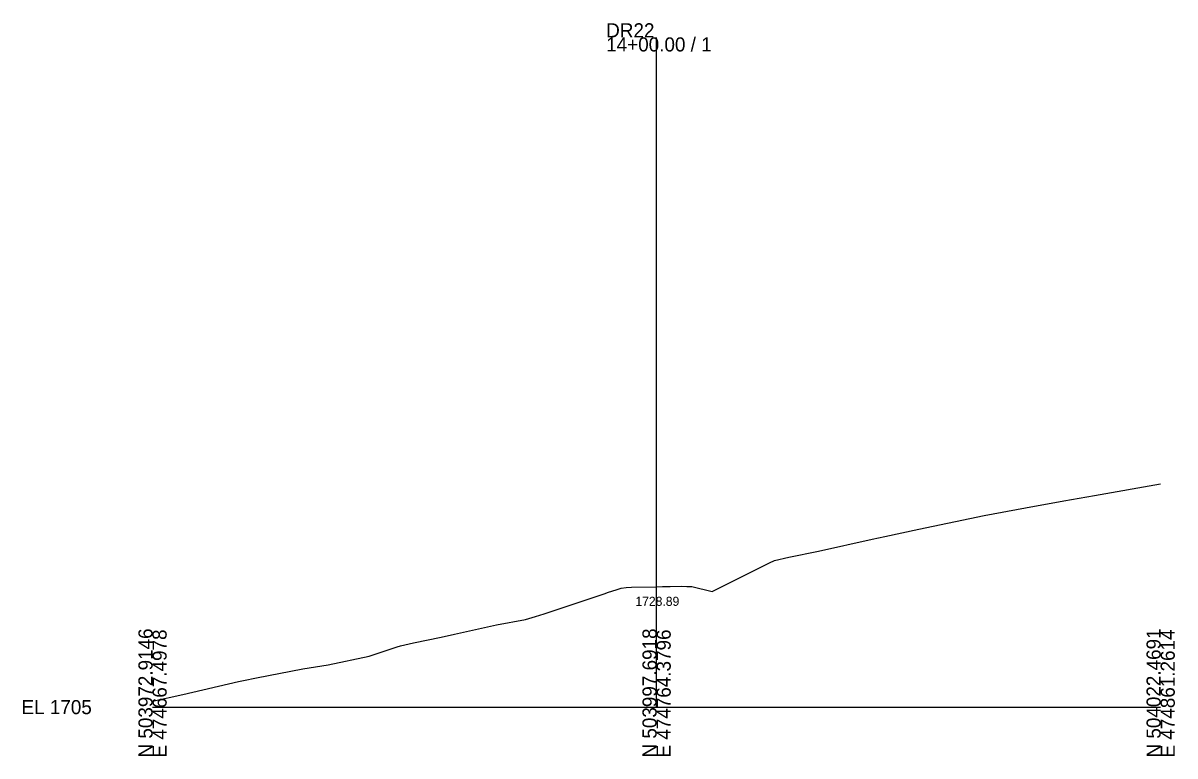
# Model space of a CAD drawing. Extents: x -26 to 1203, y -10 to 9633.
# Drawn here: x 974.3 to 1202.8, y -9.7 to 135.7 of the extents above; entities that cross this region are included whole.
import ezdxf

# ---------------------------------------------------------------- set-up
doc = ezdxf.new("R2010")
doc.units = 0
for name, color, linetype in [('Exist Cross Section Cell', 7, 'Continuous'), ('Exist XS Center Line Elevation Label', 7, 'Continuous'), ('Exist XS Ground Line', 7, 'Continuous'), ('Scratch_Level_5', 7, 'Continuous')]:
    doc.layers.add(name, color=color, linetype=linetype)

msp = doc.modelspace()

# ---------------------------------------------------------------- linework, layer by layer
at = {"layer": 'Exist Cross Section Cell'}
for p, q in [((1100, 0), (1100, 132.88)), ((1000, 0), (1100, 0)), ((1100, 0), (1200, 0))]:
    msp.add_line(p, q, dxfattribs=at)
at = {"layer": 'Exist XS Ground Line'}
msp.add_lwpolyline([(1000, 1.16), (1006.01, 2.48), (1017.02, 5.05), (1018.07, 5.29), (1020.62, 5.8), (1029.81, 7.57), (1034.86, 8.42), (1042.95, 10.12), (1048.51, 11.97), (1049.18, 12.13), (1051.79, 12.74), (1057.26, 13.9), (1059.92, 14.48), (1068.21, 16.31), (1073.96, 17.39), (1076, 17.97), (1077.69, 18.53), (1089, 22.3), (1089.81, 22.57), (1090.29, 22.73), (1092.16, 23.35), (1093, 23.63), (1093.98, 23.71), (1095, 23.79), (1100, 23.89), (1101.18, 23.92), (1102.69, 23.95), (1105, 23.99), (1106.02, 23.95), (1107, 23.91), (1111, 22.91), (1116.19, 25.51), (1118.86, 26.84), (1122.37, 28.6), (1123.38, 29.11), (1126.24, 29.76), (1132.1, 30.95), (1142.79, 33.32), (1145.27, 33.88), (1152.02, 35.32), (1164.98, 38), (1173.21, 39.54), (1180.8, 40.9), (1186.87, 41.96), (1200, 44.29)], dxfattribs=at)
at = {"layer": 'Scratch_Level_5'}
msp.add_lwpolyline([(1000, 1.16), (1006.01, 2.48), (1017.02, 5.05), (1018.07, 5.29), (1020.62, 5.8), (1029.81, 7.57), (1034.86, 8.42), (1042.95, 10.12), (1048.51, 11.97), (1049.18, 12.13), (1051.79, 12.74), (1057.26, 13.9), (1059.92, 14.48), (1068.21, 16.31), (1073.96, 17.39), (1076, 17.97), (1077.69, 18.53), (1089, 22.3), (1089.81, 22.57), (1090.29, 22.73), (1092.16, 23.35), (1093, 23.63), (1093.98, 23.71), (1095, 23.79), (1100, 23.89), (1101.18, 23.92), (1102.69, 23.95), (1105, 23.99), (1106.02, 23.95), (1107, 23.91), (1111, 22.91), (1116.19, 25.51), (1118.86, 26.84), (1122.37, 28.6), (1123.38, 29.11), (1126.24, 29.76), (1132.1, 30.95), (1142.79, 33.32), (1145.27, 33.88), (1152.02, 35.32), (1164.98, 38), (1173.21, 39.54), (1180.8, 40.9), (1186.87, 41.96), (1200, 44.29)], dxfattribs=at)

# ---------------------------------------------------------------- texts
at = {"layer": 'Exist Cross Section Cell'}
for s, p in [('DR22', (1090, 132.88)), ('14+00.00 / 1', (1090, 130.08)), ('EL 1705', (974, -1.4))]:
    msp.add_text(s, height=2.8, dxfattribs=at).set_placement(p)
for s, p in [('N 503972.9146', (1000, -10)), ('E 474667.4978', (1002.8, -10)), ('N 503997.6918', (1100, -10)), ('E 474764.3796', (1102.8, -10)), ('N 504022.4691', (1200, -10)), ('E 474861.2614', (1202.8, -10))]:
    msp.add_text(s, height=2.8, rotation=90, dxfattribs=at).set_placement(p)
at = {"layer": 'Exist XS Center Line Elevation Label'}
msp.add_text('1728.89', height=1.8, dxfattribs=at).set_placement((1095.8, 20.09))

doc.saveas('drawing.dxf')
